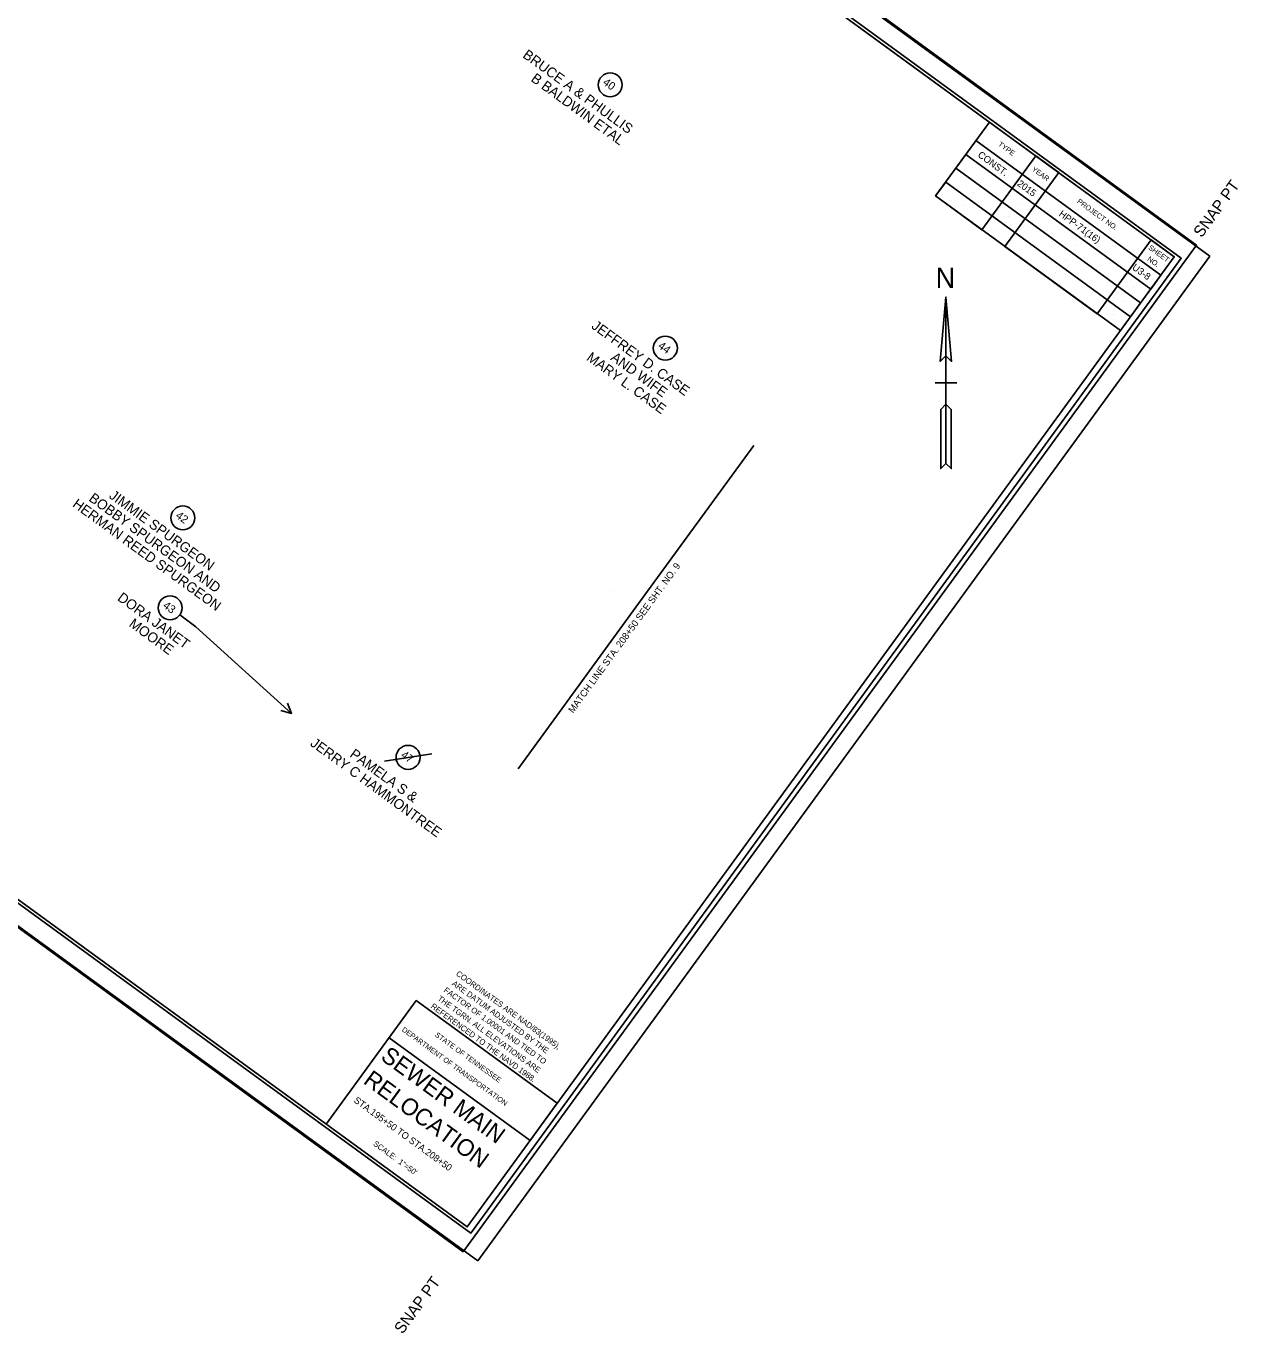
# Model space of a CAD drawing. Extents: x 2630958 to 2633078, y 566931 to 568943.
# Drawn here: x 2632018 to 2633078, y 566931 to 568075 of the extents above; entities that cross this region are included whole.
import ezdxf

# ---------------------------------------------------------------- set-up
doc = ezdxf.new("R2010")
doc.units = 0
for name, color, linetype in [('DESIGN - CENTERLINE - Proposed Text', 7, 'Continuous'), ('DESIGN - SCRATCH - User 1', 7, 'Continuous'), ('DESIGN - SHEET - Corner Text', 7, 'Continuous'), ('DESIGN - SHEET - Light Grid', 7, 'Continuous'), ('DESIGN - SHEET - Linework', 7, 'Continuous'), ('DESIGN - SHEET - Plot Shape', 7, 'Continuous'), ('SURVEY - PROPERTY - Owners', 7, 'Continuous'), ('SURVEY - PROPERTY - Tract Numbers', 7, 'Continuous')]:
    doc.layers.add(name, color=color, linetype=linetype)

msp = doc.modelspace()

# ---------------------------------------------------------------- linework, layer by layer
at = {"layer": 'DESIGN - CENTERLINE - Proposed Text'}
for p, q in [((2632822.3, 567763.1), (2632812.9, 567763.1)), ((2632831.8, 567763.1), (2632822.3, 567763.1))]:
    msp.add_line(p, q, dxfattribs=at)
for points in [[(2632822.3, 567838.1), (2632817.4, 567781.8), (2632822.3, 567786.7), (2632827.2, 567781.8), (2632822.3, 567838.1), (2632822.3, 567692.6), (2632826.9, 567688.1), (2632826.9, 567739.8), (2632822.3, 567744.4), (2632817.8, 567739.8), (2632817.8, 567688.1), (2632822.3, 567692.6)], [(2632448.1, 567425.5), (2632551.2, 567566.9), (2632654.3, 567708.4)]]:
    msp.add_lwpolyline(points, dxfattribs=at)
for points in [[(2632822.3, 567786.7), (2632827.2, 567781.8), (2632822.3, 567838.1)], [(2632817.8, 567688.1), (2632822.3, 567692.6), (2632822.3, 567744.4), (2632817.8, 567739.8)]]:
    msp.add_lwpolyline(points, close=True, dxfattribs=at)
at = {"layer": 'DESIGN - SCRATCH - User 1'}
for p, q in [((2632864.4, 567954.3), (2632864.4, 567954.3)), ((2632855.6, 567942.1), (2632855.6, 567942.1)), ((2632846.7, 567930), (2632846.7, 567930)), ((2632894.3, 567932.5), (2632894.3, 567932.5)), ((2632837.9, 567917.9), (2632837.9, 567917.9)), ((2632885.5, 567920.4), (2632885.5, 567920.4)), ((2632876.6, 567908.2), (2632876.6, 567908.2)), ((2632867.8, 567896.1), (2632867.8, 567896.1)), ((2632944.8, 567895.7), (2632944.8, 567895.7)), ((2632936, 567883.5), (2632936, 567883.5)), ((2632927.1, 567871.4), (2632927.1, 567871.4)), ((2632918.3, 567859.3), (2632918.3, 567859.3)), ((2632995.3, 567858.9), (2632995.3, 567858.9)), ((2632986.5, 567846.7), (2632986.5, 567846.7)), ((2632977.7, 567834.6), (2632977.7, 567834.6)), ((2632968.8, 567822.5), (2632968.8, 567822.5)), ((2632531.6, 567581.2), (2632531.6, 567581.2)), ((2632369.6, 567107.6), (2632369.6, 567107.6))]:
    msp.add_line(p, q, dxfattribs=at)
at = {"layer": 'DESIGN - SHEET - Light Grid'}
msp.add_lwpolyline([(2631061.2, 568000), (2632406.8, 567019.4), (2633028.1, 567872.1), (2631682.5, 568852.7)], close=True, dxfattribs=at)
at = {"layer": 'DESIGN - SHEET - Linework'}
for p, q in [((2631598.5, 568933.9), (2633053.2, 567873.8)), ((2630958.1, 568055.1), (2632412.8, 566995)), ((2633053.2, 567873.8), (2632412.8, 566995))]:
    msp.add_line(p, q, dxfattribs=at)
for points in [[(2631749.8, 568800.5), (2631131.4, 567952), (2632403.6, 567024.8), (2633022, 567873.4), (2631749.8, 568800.5)], [(2632860.4, 567991.2), (2632813.3, 567926.6), (2632974.9, 567808.8), (2633022, 567873.4), (2633001.8, 567888.2), (2632954.7, 567823.5), (2632873.9, 567882.4), (2632921, 567947), (2632900.8, 567961.8), (2632853.7, 567897.1), (2632813.3, 567926.6), (2632822.1, 567938.7), (2632983.7, 567820.9), (2632992.6, 567833), (2632830.9, 567950.8), (2632839.8, 567962.9), (2633001.4, 567845.1), (2633010.2, 567857.3), (2632848.6, 567975.1)], [(2632280.4, 567114.7), (2632359.1, 567222.7), (2632482.3, 567132.9), (2632458.8, 567100.5), (2632335.5, 567190.3)]]:
    msp.add_lwpolyline(points, dxfattribs=at)
at = {"layer": 'DESIGN - SHEET - Plot Shape'}
for points in [[(2631667.7, 568884.8), (2633041.6, 567883.5), (2632400, 567003.1), (2631026.1, 568004.3)], [(2631681.1, 568850.6), (2633022, 567873.4), (2632403.6, 567024.8), (2631062.7, 568002)]]:
    msp.add_lwpolyline(points, close=True, dxfattribs=at)
at = {"layer": 'SURVEY - PROPERTY - Tract Numbers'}
msp.add_line((2632331.2, 567432.2), (2632372.6, 567438.7), dxfattribs=at)
for points in [[(2632166.4, 567549.8), (2632152.3, 567560.1)], [(2632249.9, 567473.9), (2632166.4, 567549.8)], [(2632246.4, 567483), (2632249.9, 567473.9), (2632240.5, 567476.5)]]:
    msp.add_lwpolyline(points, dxfattribs=at)
for centre in [(2632528.7, 568023.8), (2632576.9, 567793.5), (2632154.9, 567645), (2632143.8, 567566.3), (2632351.9, 567435.5)]:
    msp.add_circle(centre, 10.5, dxfattribs=at)

# ---------------------------------------------------------------- texts
at = {"layer": 'DESIGN - CENTERLINE - Proposed Text'}
msp.add_text('N', height=17.7, dxfattribs=at).set_placement((2632813.3, 567846.1))
msp.add_text('MATCH LINE STA. 208+50 SEE SHT. NO. 9', height=6, rotation=53.918, dxfattribs=at).set_placement((2632496.3, 567473.7))
at = {"layer": 'DESIGN - SHEET - Corner Text'}
for s, height, rotation, p in [('TYPE', 4.5, 323.918, (2632867.5, 567970.9)), ('CONST.', 6, 323.918, (2632849.6, 567961.4)), ('YEAR', 4.5, 323.918, (2632897.1, 567949.1)), ('2015', 6, 323.918, (2632884.1, 567936.2)), ('  SNAP PT', 10, 53.918, (2633041.6, 567883.5)), ('PROJECT NO.', 4.5, 323.918, (2632936.6, 567920.9)), ('HPP-71(16)', 6, 323.918, (2632920.5, 567909.7)), ('SHEET', 4.5, 323.918, (2632998.9, 567880.5)), ('NO.', 4.5, 323.918, (2632998, 567870.5)), ('U3-8', 6, 323.918, (2632984.6, 567862.9)), ('COORDINATES ARE NAD/83(1995),', 5, 323.918, (2632393.3, 567245.2)), ('FACTOR OF 1.00001 AND TIED TO', 5, 323.918, (2632382.6, 567230.8)), ('ARE DATUM ADJUSTED BY THE', 5, 323.918, (2632389.8, 567236.6)), ('REFERENCED TO THE NAVD 1988.', 5, 323.918, (2632371.3, 567216.7)), ('THE TGRN. ALL ELEVATIONS ARE', 5, 323.918, (2632377.2, 567223.5)), ('DEPARTMENT OF TRANSPORTATION', 4.5, 323.918, (2632346, 567196.4)), ('STATE OF TENNESSEE', 4.5, 323.918, (2632375, 567191.8)), ('SEWER MAIN', 14.76, 323.918, (2632327, 567171.7)), ('RELOCATION', 14.76, 323.918, (2632311.9, 567150.9)), ('STA.195+50 TO STA.208+50', 5.906, 323.918, (2632303.9, 567134.3)), ('SCALE:  1"=50\'', 4.921, 323.918, (2632321, 567096.5)), ('SNAP PT  ', 10, 53.918, (2632347, 566930.4))]:
    msp.add_text(s, height=height, rotation=rotation, dxfattribs=at).set_placement(p)
at = {"layer": 'SURVEY - PROPERTY - Owners'}
for s, p in [('BRUCE A & PHULLIS ', (2632451.5, 568048.3)), ('B BALDWIN ETAL', (2632458.7, 568027.6)), ('JEFFREY D. CASE', (2632511.6, 567811.4)), ('MARY L. CASE', (2632507.3, 567783.6)), ('AND WIFE', (2632528.4, 567783.7)), ('BOBBY SPURGEON AND', (2632072, 567660.5)), ('JIMMIE SPURGEON', (2632089.7, 567663)), ('HERMAN REED SPURGEON', (2632057.7, 567655.4)), ('DORA JANET', (2632097, 567573.5)), ('MOORE', (2632107.1, 567550.7)), ('JERRY C HAMMONTREE', (2632265.7, 567446.3)), ('PAMELA S &', (2632300.2, 567436.6))]:
    msp.add_text(s, height=8.75, rotation=323.918, dxfattribs=at).set_placement(p)
at = {"layer": 'SURVEY - PROPERTY - Tract Numbers'}
for s, p in [('40', (2632521.6, 568024.7)), ('44', (2632569.9, 567794.2)), ('42', (2632148, 567645.7)), ('43', (2632136.9, 567567)), ('47', (2632345, 567436.2))]:
    msp.add_text(s, height=7, rotation=323.918, dxfattribs=at).set_placement(p)

doc.saveas('drawing.dxf')
